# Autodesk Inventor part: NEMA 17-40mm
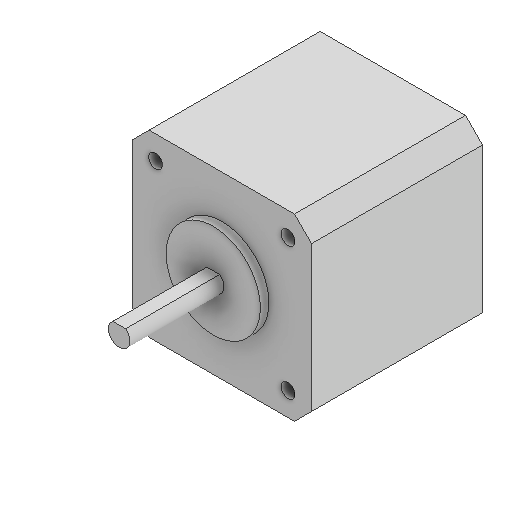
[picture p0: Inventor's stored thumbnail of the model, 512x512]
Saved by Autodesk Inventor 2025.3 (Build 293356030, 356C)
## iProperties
Created: 2026-03
Part Number: NEMA 17-40mm
Material: Generico
Description: NEMA 17
Document SubType Name: Modeling
Designer: R5800u
Density: 1 g/cm^3
Appearance: Default
Author: R5800u
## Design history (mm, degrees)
node "NEMA 17"
sketch "Schizzo1"
  geometry: L1 (-2.707, 42)-(39.293, 42); L2 (39.293, 42)-(39.293, 0); L3 (39.293, 0)-(-2.707, 0); L4 (-2.707, 0)-(-2.707, 42); L5 (-2.707, 42)-(39.293, 0); L6 (39.293, 42)-(-2.707, 0); L7 (50.204, 58.756)-(-13.618, 58.756); L8 (-13.618, 58.756)-(-13.618, -16.756); L9 (-13.618, -16.756)-(50.204, -16.756); L10 (50.204, -16.756)-(50.204, 58.756); L11 (50.204, 58.756)-(-13.618, -16.756); L12 (-13.618, 58.756)-(50.204, -16.756); A1 r 2.5 centre (18.293, 21) between (16.793, 23) and (19.793, 23) reference; 1 further point
  constraints: 24 end point, 4 midpoint, 4 parallel, 2 horizontal, 2 perpendicular
  dimensions: "d0" = 42 distance of L2.end L3.end; "d1" = 42 distance of L1.end L2.end
extrude "Estrusione1" cut sketch "Schizzo1" extent not by distance; stored distance "d2" = 0; taper "d3" = 0 deg
sketch "Schizzo2"
  geometry: L1 (1.5, 2)-(-1.5, 2) reference; A1 r 2.5 centre (0, 0) between (-1.5, 2) and (1.5, 2) reference; 1 further point
extrude "Estrusione2" cut sketch "Schizzo2" distance "d4" = 1; taper "d5" = 0 deg
chamfer "Smusso1" distance "d6" = 4; stored, may be unused: second distance "d7" = 2, angle "d8" = 45 deg
sketch "Schizzo3"
  geometry: L1 (38, -38)-(34, -42) reference; L2 (38, -38)-(38, -4) reference; L3 (34, 0)-(38, -4) reference; L4 (34, 0)-(0, 0) reference; L5 (-4, -4)-(0, 0) reference; L6 (-4, -4)-(-4, -38) reference; L7 (0, -42)-(-4, -38) reference; L8 (0, -42)-(34, -42) reference; C1 r 1.6 at (1.5, -5.5) reference; C2 r 1.6 at (1.5, -36.5) reference; C3 r 1.6 at (32.5, -36.5) reference; C4 r 1.6 at (32.5, -5.5) reference; 1 further point
extrude "Estrusione3" join sketch "Schizzo3" distance "d9" = 2; taper "d10" = 0 deg
node "Solido1"
node "Linea chiusa proiettata1"
node "Linea chiusa proiettata2"
